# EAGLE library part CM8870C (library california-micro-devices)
CMOS Integrated DTMF Receiver cm8870.pdf
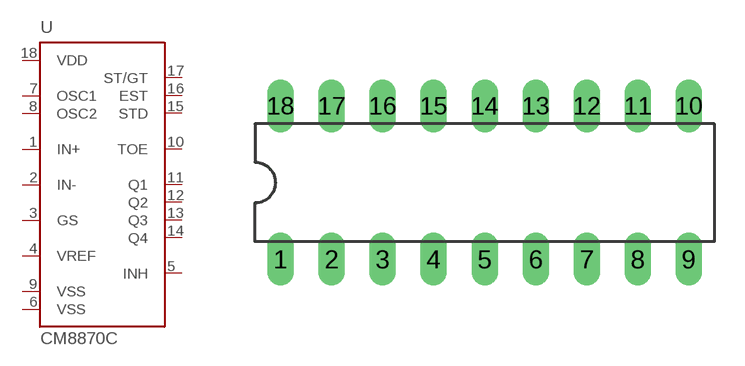
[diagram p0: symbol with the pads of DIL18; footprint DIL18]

Designator prefix -

## CM8870CP  [DIL18]
1  IN+  in
2  IN-  in
3  GS  in
4  VREF  out
5  INH  in
6  VSS  pwr
7  OSC1  in
8  OSC2
9  VSS  pwr
10  TOE  in
11  Q1  out
12  Q2  out
13  Q3  out
14  Q4  out
15  STD  in
16  EST  in
17  ST/GT
18  VDD  pwr

## Footprint DIL18 (pad centres in mm)
Dual In Line Package
drill 0.813 long: 1 -10.16,-3.81; 2 -7.62,-3.81; 3 -5.08,-3.81; 4 -2.54,-3.81; 5 0,-3.81; 6 2.54,-3.81; 7 5.08,-3.81; 8 7.62,-3.81; 9 10.16,-3.81; 10 10.16,3.81; 11 7.62,3.81; 12 5.08,3.81; 13 2.54,3.81; 14 0,3.81; 15 -2.54,3.81; 16 -5.08,3.81; 17 -7.62,3.81; 18 -10.16,3.81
